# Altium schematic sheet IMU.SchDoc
size A3
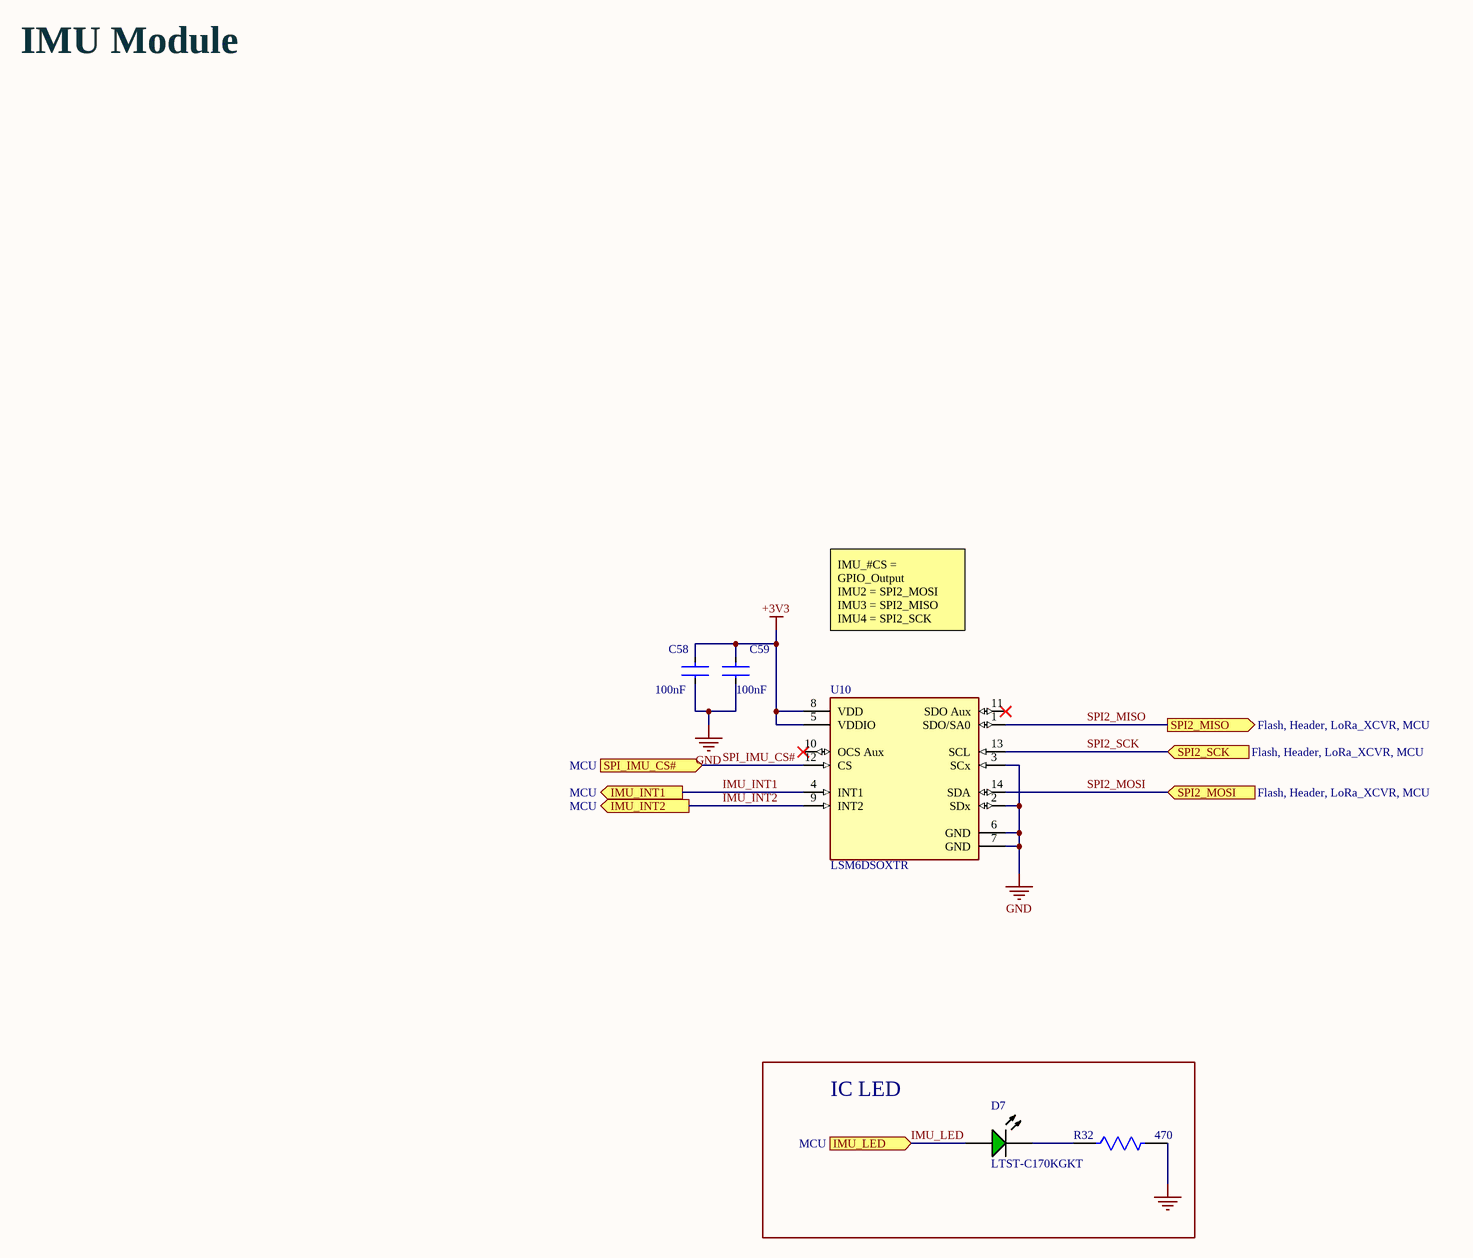
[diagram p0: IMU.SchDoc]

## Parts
C58  100nF  [FP-GRM15-MFG]
C59  100nF  [FP-GRM15-MFG]
D7  LTST-C170KGKT  [LTST-LTST-C170KGKT-2_V]
R32  470  [FP-CPF0603-MFG]
U10  LSM6DSOXTR  [FP-LGA-14L-DM00249496-MFG]

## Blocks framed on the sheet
IC LED: D7 R32

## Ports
IMU_INT1 (out, see MCU), IMU_INT2 (out, see MCU), IMU_LED (in, see MCU), SPI2_MISO (out, see Flash, Header, LoRa_XCVR, MCU), SPI2_MOSI (in, see Flash, Header, LoRa_XCVR, MCU), SPI2_SCK (in, see Flash, Header, LoRa_XCVR, MCU), SPI_IMU_CS# (in, see MCU)

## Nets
+3V3: C58.2 C59.2 U10.5(VDDIO) U10.8(VDD)
GND: C58.1 C59.1 R32.2 U10.2(SDx) U10.3(SCx) U10.6(GND) U10.7(GND)
IMU_INT1: U10.4(INT1) ; port IMU_INT1
IMU_INT2: U10.9(INT2) ; port IMU_INT2
IMU_LED: D7.2(A) ; port IMU_LED
SPI2_MISO: U10.1(SDO/SA0) ; port SPI2_MISO
SPI2_MOSI: U10.14(SDA) ; port SPI2_MOSI
SPI2_SCK: U10.13(SCL) ; port SPI2_SCK
SPI_IMU_CS#: U10.12(CS) ; port SPI_IMU_CS#
NetD7_1: D7.1(K) R32.1

Not connected (* = marked no-connect by the designer): U10 10(OCS_Aux)* 11(SDO_Aux)*

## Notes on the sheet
- IMU Module
- IMU_#CS = GPIO_Output
  IMU2 = SPI2_MOSI
  IMU3 = SPI2_MISO
  IMU4 = SPI2_SCK

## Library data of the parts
C58 C59 = CMP-2100-03641-2: CAP CER 0.1UF 16V X7R 0402; Manufacturer Part Number: GRM155R71C104KA88D; Manufacturer: Murata; Standoff Height: 0mm; Tolerance: 10%; Description: CAP Ceramic 0.10μF 10% X7R 16Vdc 0402 SMD; Voltage Rating: 16Vdc; Material: Ceramic; Capacitance: 0.10μF; Value: 0.10μF
D7 = CMP-2000-06620-1: Ultra Bright AlInGaP Chip LED, 75 mW, -55 to 85 degC, 2-Pin SMD (0805), RoHS, Tape and Reel; Manufacturer: Lite-On; Forward Current: 30mA; Power Dissipation Max: 75mW; Emitting Color: YellowGreen; Type: Uni-Color; Forward Voltage: 2.4V; Dominant Wave Length: 571nm; Test Current (It): 20mA; Product Length (mm): 2mm; Peak Wavelength: 574nm; Power Dissipation: 75W; Product Depth (mm): 1.25mm; DELETED: Compliant; High Brightness: Yes; Product Height (mm): 1.1mm; Luminous Intensity: 35mcd; Shape Type: Rectangular; Chip Material: AlGaInP; Viewing Angle: 130deg; Number of  Elements: 1; Reverse Voltage: 5V; Rad Hardened: No
R32 = CMP-03211-004765-1: RES SMD 470Ω 0.1% 1/16W 0603 / CPF0603B470RE; Manufacturer: TE Connectivity; Temperature Coefficient: 25ppm/°C; Voltage Rating: 50V; Power Rating: 0.063W
U10 = CMP-12177-000010-1: INEMO INERTIAL MODULE: 3D ACCELE; Manufacturer: STMicroelectronics; Sensor Type: Temperature,Accelerometer,Gyroscope; Accel Range: 2/4/8/16g; Accel Sensitivity: 0.061/0.122/0.244/0.488mV/g; Operating Supply Current: 0.55mA; Gyro Range: 125/250/500/1000/2000°/s; Gyro Sensitivity: 4.375/8.75/17.5/35/70LSB/°/s; Sensor Output: I2C,SPI,Other; Min Supply Voltage: 1.62V; Max Supply Voltage: 3.6V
